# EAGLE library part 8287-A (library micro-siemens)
MICROPROCESSOR/PERIPHERAL DEVICE
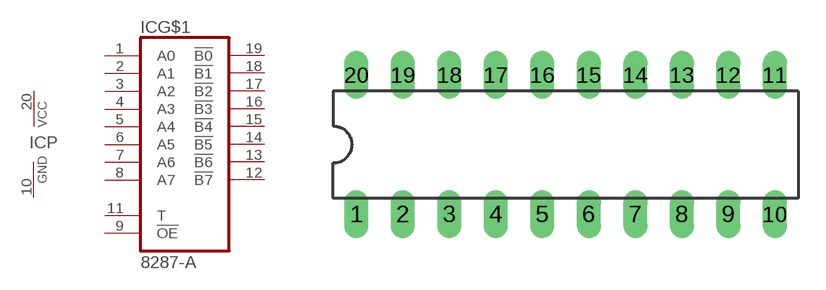
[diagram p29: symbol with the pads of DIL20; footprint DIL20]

Designator prefix IC; gates G$1=8287-A P=VCCGND

## 8287-A (OC_FARNELL: unknown; OC_NEWARK: unknown)  [DIL20]
1  G$1:A0
2  G$1:A1
3  G$1:A2
4  G$1:A3
5  G$1:A4
6  G$1:A5
7  G$1:A6
8  G$1:A7
9  G$1:!OE  in
10  P:GND  pwr
11  G$1:T  in
12  G$1:!B7
13  G$1:!B6
14  G$1:!B5
15  G$1:!B4
16  G$1:!B3
17  G$1:!B2
18  G$1:!B1
19  G$1:!B0
20  P:VCC  pwr

## Footprint DIL20 (pad centres in mm)
Dual In Line Package
drill 0.813 long: 1 -11.43,-3.81; 2 -8.89,-3.81; 3 -6.35,-3.81; 4 -3.81,-3.81; 5 -1.27,-3.81; 6 1.27,-3.81; 7 3.81,-3.81; 8 6.35,-3.81; 9 8.89,-3.81; 10 11.43,-3.81; 11 11.43,3.81; 12 8.89,3.81; 13 6.35,3.81; 14 3.81,3.81; 15 1.27,3.81; 16 -1.27,3.81; 17 -3.81,3.81; 18 -6.35,3.81; 19 -8.89,3.81; 20 -11.43,3.81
